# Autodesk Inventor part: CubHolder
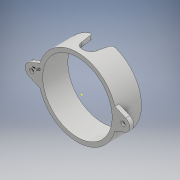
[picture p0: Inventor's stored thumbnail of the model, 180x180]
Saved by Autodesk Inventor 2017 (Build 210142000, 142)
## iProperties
Created: 2016-12
Part Number: CubHolder
Material: Generic
Document SubType Name: Modeling
Designer: Dans
Density: 1 g/cm^3
Appearance: Default
Author: Dans
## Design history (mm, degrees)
sketch "Sketch1"
  geometry: C1 r 41.5 at (0, 0); C2 r 46.5 at (0, 0); 1 further point
  constraints: 2 centre point, 2 coincident
  dimensions: "d0" = 83 diameter of C1; "d1" = 93 diameter of C2
extrude "Extrusion1" new body sketch "Sketch1" distance "d2" = 30; taper "d3" = 0 deg
sketch "Sketch2"
  geometry: L1 (0, 0)-(0, 6); L2 (0, 6)-(0, 15); L3 (-8.846, 13.343)-(-11.988, 30.115); L4 (8.846, 13.343)-(11.988, 30.115); L5 (-11.988, 30.115)-(11.988, 30.115); L6 (41.5, 0)-(-41.5, 0) reference; A1 r 9 centre (0, 15) between (-8.846, 13.343) and (0, 6); A2 r 9 centre (0, 15) between (0, 6) and (8.846, 13.343)
  constraints: 10 end point, 4 point on circle, 2 centre point, 2 symmetric about line, 2 vertical, 1 coincident, 1 parallel, 1 tangent, 1 other
  dimensions: "d4" = 6 distance of L1.start L1.end; "d5" = 9 distance of L1.end L2.end
extrude "Extrusion2" cut sketch "Sketch2" distance "d6" = 63.25; taper "d7" = 0 deg
fillet "Fillet1" dims "d8" = 4
sketch "Sketch3"
  geometry: L1 (0, 0)-(46.5, 0); L2 (57.676, -7.343)-(44.653, -12.975); L3 (57.676, 7.343)-(44.653, 12.975); L4 (0, 0)-(0, -19.306); L5 (0, 0)-(-46.5, 0); L6 (-57.676, -7.343)-(-44.653, -12.975); L7 (-57.676, 7.343)-(-44.653, 12.975); C1 r 2.6 at (54.5, 0); C2 r 2.6 at (-54.5, 0); A1 r 46.5 centre (0, 0) between (46.5, 0) and (44.653, -12.975) reference; A2 r 8 centre (54.5, 0) between (57.676, -7.343) and (62.5, 0); A3 r 8 centre (54.5, 0) between (62.5, 0) and (57.676, 7.343); A4 r 46.5 centre (0, 0) between (44.653, -12.975) and (44.653, 12.975); A5 r 46.5 centre (0, 0) between (-46.5, 0) and (-44.653, -12.975); A6 r 8 centre (-54.5, 0) between (-62.5, 0) and (-57.676, -7.343); A7 r 8 centre (-54.5, 0) between (-57.676, 7.343) and (-62.5, 0); A8 r 46.5 centre (0, 0) between (-44.653, 12.975) and (-44.653, -12.975)
  constraints: 18 point on circle, 14 end point, 9 centre point, 8 symmetric about line, 2 coincident, 1 horizontal, 1 tangent, 1 vertical, 5 other
  dimensions: "d11" = 5.2 diameter of C1
extrude "Extrusion3" join sketch "Sketch3" distance "d12" = 5; taper "d13" = 0 deg
sketch "Sketch4"
  geometry: C1 r 2.6 at (-54.5, 0) reference; C2 r 5 at (-54.5, 0); 1 further point
  constraints: 1 centre point, 1 coincident
  dimensions: "d14" = 10 diameter of C2
chamfer "Chamfer1" distance "d15" = 2.4; stored, may be unused: second distance "d16" = 2, angle "d17" = 45 deg
body "Solid1"
